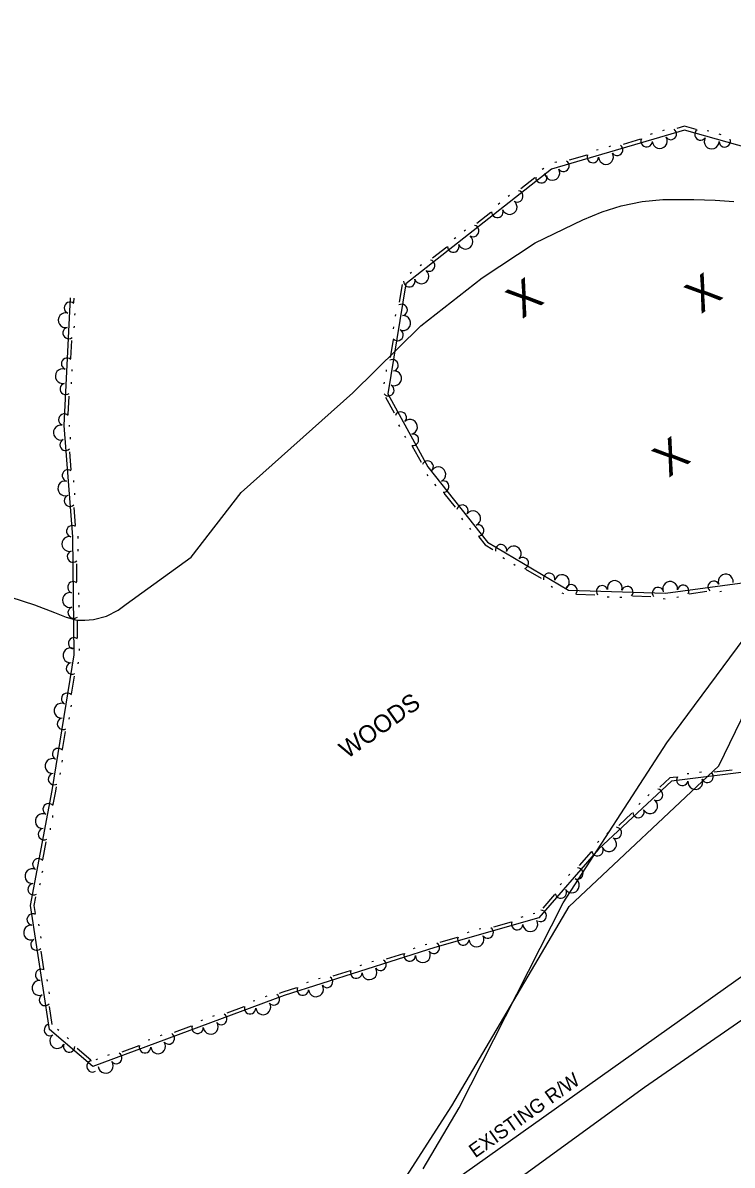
# Model space of a CAD drawing. Extents: x 1577032 to 1581865, y 611492 to 615011.
# Drawn here: x 1578939.3 to 1579100.2, y 612864.7 to 613124 of the extents above; entities that cross this region are included whole.
import ezdxf

# ---------------------------------------------------------------- set-up
doc = ezdxf.new("R2010")
doc.units = 0
for name, color, linetype in [('Exist Hydro Jurisdictional Stream or Body of Water', 7, 'Continuous'), ('Exist Right of Way Line', 7, 'Continuous'), ('Exist Right of Way Line Text', 7, 'Continuous'), ('Exist Utilities Telephone UG FO SUE LOS B', 7, 'Continuous'), ('Exist Utilities Water UG Line SUE LOS B', 7, 'Continuous'), ('Exist Vegetation Tree CELL', 7, 'Continuous'), ('Exist Vegetation Woods Line Text', 7, 'Continuous'), ('Old_Level_11', 7, 'Continuous'), ('Old_Level_8', 7, 'Continuous'), ('Scratch_Level_4', 7, 'Continuous')]:
    doc.layers.add(name, color=color, linetype=linetype)

msp = doc.modelspace()

# ---------------------------------------------------------------- linework, layer by layer
at = {"layer": 'Exist Hydro Jurisdictional Stream or Body of Water'}
msp.add_lwpolyline([(1578931.12, 612995.38), (1578941.94, 612991.91), (1578946.47, 612990.14), (1578949.11, 612989.07), (1578951.53, 612988.4), (1578953.33, 612988.4), (1578955.36, 612988.57), (1578958.28, 612989.3), (1578960.93, 612990.65), (1578962.72, 612992.06), (1578977.46, 613002.69), (1578988.86, 613017.41), (1579014.13, 613040.04), (1579029.62, 613055.18), (1579043.54, 613066.13), (1579055.52, 613074.04), (1579066.31, 613079.26), (1579070.77, 613081.07), (1579075.01, 613082.43), (1579079.81, 613083.39), (1579084.5, 613083.9), (1579091.56, 613083.9), (1579096.37, 613083.73), (1579100.6, 613083.39)], dxfattribs=at)
at = {"layer": 'Exist Right of Way Line'}
msp.add_lwpolyline([(1578124.38, 612213.06), (1579205.66, 612980.92)], dxfattribs=at)
at = {"layer": 'Exist Utilities Telephone UG FO SUE LOS B'}
msp.add_lwpolyline([(1579030.15, 612863.93), (1579038.32, 612877.78), (1579061.9, 612924.28), (1579085.37, 612960.54), (1579115.71, 613001.47), (1579171.23, 613028.63), (1579251.42, 613079.81), (1579314.27, 613123.97)], dxfattribs=at)
at = {"layer": 'Exist Utilities Water UG Line SUE LOS B'}
for p, q in [((1579097.19, 612955.35), (1579118.18, 612998.65)), ((1579063.25, 612923.46), (1579097.19, 612955.35)), ((1579036.61, 612878.17), (1579063.25, 612923.46)), ((1579016.46, 612846.84), (1579036.61, 612878.17))]:
    msp.add_line(p, q, dxfattribs=at)
at = {"layer": 'Old_Level_11'}
for points in [[(1579092.06, 613099.75), (1579089.38, 613100.51), (1579087.67, 613100)], [(1579122.8, 613090.25), (1579089.39, 613099.65), (1579059.25, 613090.73), (1579026.21, 613064.72), (1579022.09, 613039.75), (1579031.17, 613023.18), (1579044.7, 613006.12), (1579063.07, 612995.2), (1579085.08, 612994.52), (1579110.94, 612997.99)], [(1579079.41, 613097.55), (1579075.47, 613096.39)], [(1579082.04, 613098.76), (1579081.65, 613098.65)], [(1579084.8, 613099.58), (1579084.4, 613099.46)], [(1579094.94, 613099.37), (1579094.54, 613099.48)], [(1579097.7, 613098.59), (1579097.31, 613098.7)], [(1579069.85, 613095.16), (1579069.46, 613095.04)], [(1579072.6, 613095.97), (1579072.21, 613095.85)], [(1579060.41, 613092.36), (1579060.02, 613092.25)], [(1579067.22, 613093.95), (1579063.28, 613092.78)], [(1579057.47, 613090.9), (1579057.15, 613090.65)], [(1579055.47, 613088.8), (1579052.25, 613086.27)], [(1579049.74, 613084.81), (1579049.42, 613084.56)], [(1579047.48, 613083.04), (1579047.16, 613082.78)], [(1579045.48, 613080.94), (1579042.26, 613078.4)], [(1579039.75, 613076.95), (1579039.43, 613076.7)], [(1579037.5, 613075.17), (1579037.17, 613074.92)], [(1579035.49, 613073.07), (1579032.27, 613070.54)], [(1579029.76, 613069.08), (1579029.44, 613068.83)], [(1579027.51, 613067.31), (1579027.19, 613067.05)], [(1579025.36, 613064.6), (1579024.69, 613060.56)], [(1579104.69, 612954.14), (1579086.47, 612951.84), (1579069.9, 612936.48), (1579056.38, 612920.84), (1579032.79, 612914.13), (1578998.56, 612903.2), (1578955.18, 612887.09), (1578945.32, 612895.5), (1578941.05, 612923.66), (1578945.95, 612949.77), (1578950.95, 612980.58), (1578950.61, 613007.31), (1578948.63, 613032.57), (1578950.08, 613061.56)], [(1578950.85, 613060.51), (1578950.9, 613061.52)], [(1578951.12, 613057.62), (1578951.14, 613058.03)], [(1579023.82, 613057.79), (1579023.76, 613057.39)], [(1578950.97, 613054.75), (1578950.99, 613055.16)], [(1579023.36, 613054.96), (1579023.29, 613054.56)], [(1578950.21, 613047.81), (1578950.42, 613051.9)], [(1579023.29, 613052.06), (1579022.62, 613048.02)], [(1578950.48, 613044.92), (1578950.5, 613045.33)], [(1579021.75, 613045.25), (1579021.69, 613044.84)], [(1578950.33, 613042.05), (1578950.35, 613042.46)], [(1579021.28, 613042.42), (1579021.22, 613042.01)], [(1578949.57, 613035.11), (1578949.78, 613039.21)], [(1579021.55, 613039.03), (1579023.52, 613035.43)], [(1579024.54, 613032.72), (1579024.74, 613032.36)], [(1578949.87, 613032.38), (1578949.86, 613032.59), (1578949.86, 613032.63)], [(1579025.92, 613030.2), (1579026.12, 613029.84)], [(1578950.1, 613029.52), (1578950.07, 613029.93)], [(1579027.66, 613027.88), (1579029.63, 613024.28)], [(1578950.24, 613022.54), (1578949.92, 613026.63)], [(1578950.87, 613019.71), (1578950.84, 613020.12)], [(1579030.93, 613021.5), (1579031.18, 613021.18)], [(1578951.1, 613016.85), (1578951.06, 613017.25)], [(1579032.71, 613019.25), (1579032.97, 613018.93)], [(1579034.82, 613017.26), (1579037.37, 613014.05)], [(1578951.23, 613009.86), (1578950.91, 613013.95)], [(1579038.83, 613011.54), (1579039.08, 613011.22)], [(1578951.85, 613006.95), (1578951.84, 613007.36), (1578951.84, 613007.45)], [(1579040.61, 613009.3), (1579040.86, 613008.97)], [(1579042.72, 613007.3), (1579044.15, 613005.49), (1579045.95, 613004.42)], [(1578951.88, 613004.08), (1578951.88, 613004.49)], [(1579048.21, 613002.6), (1579048.56, 613002.39)], [(1578951.56, 612997.1), (1578951.51, 613001.21)], [(1579050.68, 613001.14), (1579051.03, 613000.93)], [(1579053.35, 613000.02), (1579056.88, 612997.93)], [(1578952.01, 612994.24), (1578952, 612994.65)], [(1579059.14, 612996.11), (1579059.49, 612995.9)], [(1579061.61, 612994.64), (1579061.96, 612994.43)], [(1579064.94, 612994.32), (1579069.04, 612994.19)], [(1579077.65, 612993.93), (1579081.75, 612993.8)], [(1579090.45, 612994.41), (1579094.51, 612994.96)], [(1579097.41, 612994.93), (1579097.82, 612994.99)], [(1578952.04, 612991.37), (1578952.04, 612991.78)], [(1579071.9, 612993.7), (1579072.31, 612993.68)], [(1579074.77, 612993.61), (1579075.18, 612993.6)], [(1579084.6, 612993.31), (1579085.01, 612993.29)], [(1579087.65, 612993.62), (1579088.06, 612993.68)], [(1578951.72, 612984.39), (1578951.67, 612988.49)], [(1578952.17, 612981.53), (1578952.16, 612981.94)], [(1578951.85, 612978.47), (1578951.92, 612978.87)], [(1578950.33, 612971.65), (1578950.99, 612975.7)], [(1578950.28, 612968.75), (1578950.34, 612969.16)], [(1578949.82, 612965.92), (1578949.89, 612966.32)], [(1578948.3, 612959.1), (1578948.95, 612963.15)], [(1578948.24, 612956.2), (1578948.31, 612956.61)], [(1578947.78, 612953.37), (1578947.85, 612953.78)], [(1579087.6, 612952.81), (1579086.11, 612952.62), (1579083.82, 612950.49)], [(1579090.39, 612953.57), (1579089.99, 612953.52)], [(1579093.24, 612953.93), (1579092.84, 612953.88)], [(1579100.21, 612954.4), (1579096.14, 612953.89)], [(1578946.18, 612946.55), (1578946.76, 612949.63), (1578946.92, 612950.6)], [(1579081.43, 612948.84), (1579081.13, 612948.56)], [(1579077.5, 612944.64), (1579074.49, 612941.85)], [(1579079.33, 612946.89), (1579079.02, 612946.61)], [(1578946.06, 612943.65), (1578946.13, 612944.05)], [(1578945.53, 612940.83), (1578945.6, 612941.23)], [(1579072.11, 612940.2), (1579071.8, 612939.92)], [(1578943.84, 612934.05), (1578944.59, 612938.08)], [(1579070, 612938.25), (1579069.7, 612937.97)], [(1579068.24, 612935.81), (1579065.55, 612932.71)], [(1578943.71, 612931.16), (1578943.79, 612931.56)], [(1579063.37, 612930.8), (1579063.1, 612930.49)], [(1578943.18, 612928.34), (1578943.26, 612928.74)], [(1579061.49, 612928.63), (1579061.22, 612928.32)], [(1578942.16, 612921.82), (1578941.88, 612923.65), (1578942.25, 612925.59)], [(1579059.92, 612926.19), (1579057.24, 612923.09)], [(1579055.46, 612921.86), (1579055.07, 612921.74)], [(1578942.99, 612919.04), (1578942.93, 612919.45)], [(1579050.05, 612919.89), (1579046.11, 612918.77)], [(1579052.7, 612921.07), (1579052.3, 612920.96)], [(1578943.42, 612916.21), (1578943.36, 612916.61)], [(1579037.82, 612916.41), (1579033.88, 612915.29)], [(1579040.47, 612917.59), (1579040.08, 612917.48)], [(1579043.23, 612918.38), (1579042.84, 612918.27)], [(1579028.25, 612913.97), (1579027.86, 612913.84)], [(1579030.98, 612914.84), (1579030.59, 612914.72)], [(1578944.06, 612909.25), (1578943.45, 612913.31)], [(1579018.87, 612910.98), (1579018.48, 612910.85)], [(1579025.64, 612912.71), (1579021.73, 612911.46)], [(1579013.53, 612908.84), (1579009.62, 612907.59)], [(1579016.13, 612910.1), (1579015.74, 612909.98)], [(1578944.9, 612906.47), (1578944.84, 612906.88)], [(1579004.02, 612906.24), (1579003.63, 612906.11)], [(1579006.76, 612907.11), (1579006.37, 612906.99)], [(1578945.33, 612903.64), (1578945.27, 612904.04)], [(1579001.41, 612904.97), (1578998.29, 612903.98), (1578997.48, 612903.68)], [(1578945.97, 612896.68), (1578945.35, 612900.74)], [(1578989.41, 612900.68), (1578985.57, 612899.25)], [(1578991.96, 612902.06), (1578991.57, 612901.92)], [(1578994.65, 612903.06), (1578994.26, 612902.92)], [(1578982.73, 612898.63), (1578982.35, 612898.49)], [(1578947.48, 612895.27), (1578947.17, 612895.54)], [(1578977.49, 612896.25), (1578973.65, 612894.82)], [(1578980.04, 612897.63), (1578979.66, 612897.49)], [(1578949.67, 612893.41), (1578949.36, 612893.67)], [(1578968.12, 612893.21), (1578967.74, 612893.07)], [(1578970.81, 612894.21), (1578970.43, 612894.06)], [(1578954.71, 612888.57), (1578951.59, 612891.23)], [(1578965.58, 612891.82), (1578961.73, 612890.4)], [(1578956.21, 612888.78), (1578955.82, 612888.64)], [(1578958.9, 612889.78), (1578958.51, 612889.64)]]:
    msp.add_lwpolyline(points, dxfattribs=at)
for centre, radius, start, end in [((1579080.82, 613097.12), 1.3, 157.2491, 358.0456), ((1579083.8, 613097.14), 1.69, 182.4443, 30.5168), ((1579086.32, 613098.75), 1.3, 214.9155, 55.7121), ((1579093.02, 613098.63), 1.3, 125.0557, 325.8523), ((1579095.57, 613097.06), 1.69, 150.251, 358.3235), ((1579098.55, 613097.08), 1.3, 182.7222, 23.5188), ((1579074.13, 613095.14), 1.3, 214.9155, 55.7121), ((1579061.94, 613091.53), 1.3, 214.9155, 55.7121), ((1579068.63, 613093.51), 1.3, 157.2491, 358.0456), ((1579071.61, 613093.54), 1.69, 182.4443, 30.5168), ((1579059.42, 613089.93), 1.69, 182.4443, 30.5168), ((1579056.95, 613088.92), 1.3, 178.987, 19.7836), ((1579051.47, 613084.61), 1.3, 236.6535, 77.4501), ((1579049.72, 613082.19), 1.69, 204.1823, 52.2548), ((1579046.96, 613081.06), 1.3, 178.987, 19.7836), ((1579041.48, 613076.74), 1.3, 236.6535, 77.4501), ((1579039.73, 613074.32), 1.69, 204.1823, 52.2548), ((1579036.97, 613073.19), 1.3, 178.987, 19.7836), ((1579031.49, 613068.88), 1.3, 236.6535, 77.4501), ((1579029.74, 613066.46), 1.69, 204.1823, 52.2548), ((1579026.98, 613065.33), 1.3, 178.987, 19.7836), ((1578949.97, 613059.32), 1.3, 47.892, 248.6886), ((1579025.24, 613058.81), 1.3, 279.0627, 119.8593), ((1578949.01, 613056.49), 1.69, 73.0873, 281.1598), ((1579025.58, 613055.84), 1.69, 246.5915, 94.664), ((1578949.68, 613053.58), 1.3, 105.5585, 306.355), ((1579024.3, 613053.14), 1.3, 221.3962, 62.1928), ((1578949.33, 613046.62), 1.3, 47.892, 248.6886), ((1579023.17, 613046.26), 1.3, 279.0627, 119.8593), ((1578948.37, 613043.79), 1.69, 73.0873, 281.1598), ((1579023.51, 613043.3), 1.69, 246.5915, 94.664), ((1578949.04, 613040.89), 1.3, 105.5585, 306.355), ((1579022.23, 613040.6), 1.3, 221.3962, 62.1928), ((1579025.03, 613034.39), 1.3, 317.1373, 157.9339), ((1578947.93, 613030.99), 1.69, 80.4616, 288.5341), ((1578948.69, 613033.92), 1.3, 47.892, 248.6886), ((1579027.13, 613032.27), 1.69, 284.6661, 132.7386), ((1579027.79, 613029.35), 1.3, 259.4709, 100.2674), ((1578948.97, 613028.2), 1.3, 112.9328, 313.7294), ((1578949.52, 613021.25), 1.3, 55.2663, 256.0629), ((1579031.14, 613023.24), 1.3, 317.1373, 157.9339), ((1579033.55, 613021.49), 1.69, 294.3826, 142.4551), ((1578948.92, 613018.32), 1.69, 80.4616, 288.5341), ((1579034.69, 613018.73), 1.3, 269.1874, 109.9839), ((1578949.97, 613015.52), 1.3, 112.9328, 313.7294), ((1579039.03, 613013.27), 1.3, 326.8538, 167.6504), ((1579041.45, 613011.53), 1.69, 294.3826, 142.4551), ((1578950.51, 613008.57), 1.3, 55.2663, 256.0629), ((1579042.59, 613008.77), 1.3, 269.1874, 109.9839), ((1578949.81, 613005.7), 1.69, 76.6864, 284.7589), ((1579047.78, 613004.29), 1.3, 347.7118, 188.5083), ((1579050.67, 613003.53), 1.69, 315.2406, 163.3131), ((1578950.67, 613002.84), 1.3, 109.1576, 309.9541), ((1579052.72, 613001.35), 1.3, 290.0453, 130.8419), ((1579058.71, 612997.79), 1.3, 347.7118, 188.5083), ((1578950.76, 612995.86), 1.3, 51.4911, 252.2877), ((1579061.6, 612997.03), 1.69, 315.2406, 163.3131), ((1579063.74, 612995.18), 1.3, 319.0055, 159.8021), ((1579073.6, 612995.7), 1.69, 344.2008, 192.2733), ((1579086.16, 612995.49), 1.69, 353.6075, 201.6799), ((1579096.03, 612995.99), 1.3, 26.0786, 226.8752), ((1579098.76, 612997.18), 1.69, 353.6075, 201.6799), ((1578949.97, 612992.98), 1.69, 76.6864, 284.7589), ((1579070.71, 612994.96), 1.3, 16.672, 217.4685), ((1579076.44, 612994.79), 1.3, 319.0055, 159.8021), ((1579083.41, 612994.57), 1.3, 16.672, 217.4685), ((1579089.12, 612995.06), 1.3, 328.4122, 169.2087), ((1578950.83, 612990.12), 1.3, 109.1576, 309.9541), ((1578950.92, 612983.15), 1.3, 51.4911, 252.2877), ((1578950.09, 612980.42), 1.69, 66.7534, 274.8259), ((1578950.44, 612977.45), 1.3, 99.2246, 300.0212), ((1578949.33, 612970.57), 1.3, 41.5581, 242.3547), ((1578948.06, 612967.87), 1.69, 66.7534, 274.8259), ((1578948.41, 612964.9), 1.3, 99.2246, 300.0212), ((1578947.29, 612958.02), 1.3, 41.5581, 242.3547), ((1578946.02, 612955.32), 1.69, 66.7534, 274.8259), ((1578946.37, 612952.35), 1.3, 99.2246, 300.0212), ((1579088.92, 612952.15), 1.3, 147.9897, 348.7863), ((1579094.62, 612952.87), 1.3, 205.6562, 46.4527), ((1579083.17, 612948.77), 1.3, 241.2513, 82.0479), ((1579091.87, 612951.69), 1.69, 173.185, 21.2575), ((1579081.62, 612946.22), 1.69, 208.7802, 56.8526), ((1578945.15, 612945.49), 1.3, 40.131, 240.9276), ((1579078.96, 612944.87), 1.3, 183.5849, 24.3814), ((1578943.81, 612942.82), 1.69, 65.3263, 273.3988), ((1578944.09, 612939.85), 1.3, 97.7975, 298.594), ((1579073.84, 612940.13), 1.3, 241.2513, 82.0479), ((1579069.66, 612936.2), 1.3, 189.9259, 30.7224), ((1579072.3, 612937.58), 1.69, 208.7802, 56.8526), ((1578942.8, 612933), 1.3, 40.131, 240.9276), ((1578941.47, 612930.33), 1.69, 65.3263, 273.3988), ((1579065.1, 612930.93), 1.3, 247.5923, 88.3889), ((1579063.85, 612928.22), 1.69, 215.1212, 63.1936), ((1578941.74, 612927.35), 1.3, 97.7975, 298.594), ((1579061.35, 612926.59), 1.3, 189.9259, 30.7224), ((1578941.53, 612920.48), 1.3, 59.3802, 260.1767), ((1579056.79, 612921.31), 1.3, 247.5923, 88.3889), ((1578941.15, 612917.52), 1.69, 84.5755, 292.6479), ((1579051.46, 612919.44), 1.3, 156.6481, 357.4446), ((1579054.44, 612919.44), 1.69, 181.8433, 29.9158), ((1579039.23, 612915.96), 1.3, 156.6481, 357.4446), ((1579042.22, 612915.96), 1.69, 181.8433, 29.9158), ((1579044.75, 612917.53), 1.3, 214.3145, 55.1111), ((1578942.39, 612914.8), 1.3, 117.0466, 317.8432), ((1579032.53, 612914.04), 1.3, 216.1362, 56.9328), ((1579020.42, 612910.18), 1.3, 216.1362, 56.9328), ((1579027.06, 612912.3), 1.3, 158.4698, 359.2663), ((1579030.04, 612912.39), 1.69, 183.665, 31.7375), ((1578943.44, 612907.91), 1.3, 59.3802, 260.1767), ((1579014.95, 612908.43), 1.3, 158.4698, 359.2663), ((1579017.93, 612908.52), 1.69, 183.665, 31.7375), ((1578943.05, 612904.95), 1.69, 84.5755, 292.6479), ((1579008.3, 612906.31), 1.3, 216.1362, 56.9328), ((1578944.3, 612902.23), 1.3, 117.0466, 317.8432), ((1578996.23, 612902.34), 1.3, 218.8152, 59.6118), ((1579002.83, 612904.57), 1.3, 158.4698, 359.2663), ((1579005.82, 612904.66), 1.69, 183.665, 31.7375), ((1578990.85, 612900.34), 1.3, 161.1487, 1.9453), ((1578993.83, 612900.57), 1.69, 186.344, 34.4165), ((1578984.31, 612897.91), 1.3, 218.8152, 59.6118), ((1578945.44, 612895.4), 1.3, 100.3272, 301.1237), ((1578978.93, 612895.91), 1.3, 161.1487, 1.9453), ((1578981.91, 612896.14), 1.69, 186.344, 34.4165), ((1578947.09, 612892.91), 1.69, 125.5225, 333.5949), ((1578972.4, 612893.48), 1.3, 218.8152, 59.6118), ((1578949.81, 612891.67), 1.3, 157.9936, 358.7902), ((1578960.48, 612889.06), 1.3, 218.8152, 59.6118), ((1578967.01, 612891.48), 1.3, 161.1487, 1.9453), ((1578969.99, 612891.71), 1.69, 186.344, 34.4165), ((1578955.11, 612887.15), 1.3, 100.3272, 301.1237), ((1578958.07, 612887.29), 1.69, 186.344, 34.4165)]:
    msp.add_arc(centre, radius, start, end, dxfattribs=at)
at = {"layer": 'Old_Level_8'}
msp.add_lwpolyline([(1578949, 612778.47), (1578966.35, 612793.38), (1578989.45, 612813.51), (1579016.65, 612835.66), (1579050.7, 612860.86), (1579080.37, 612882.46), (1579102.44, 612897.69), (1579125.77, 612910.99), (1579158.9, 612927.19), (1579180.94, 612938.03), (1579196.01, 612946.6), (1579242.04, 612993.41)], dxfattribs=at)
at = {"layer": 'Scratch_Level_4'}
for points in [[(1578991.07, 612725.28), (1579012.35, 612739.17), (1579031.33, 612751.38), (1579051.46, 612763.88), (1579075.01, 612777.37), (1579095.02, 612788.96), (1579114.97, 612802.08), (1579136.91, 612817.74), (1579159.19, 612837), (1579170.02, 612846.94), (1579184.02, 612858.83), (1579200.33, 612873.19), (1579214.2, 612885.73), (1579229.83, 612902.71)], [(1579027.98, 612739.86), (1579035.54, 612744.72), (1579055.5, 612757.12), (1579078.94, 612770.55), (1579099.16, 612782.26), (1579119.42, 612795.58), (1579141.78, 612811.55), (1579164.43, 612831.12), (1579175.24, 612841.04), (1579189.17, 612852.88), (1579205.57, 612867.32), (1579219.75, 612880.13), (1579235.83, 612897.6)]]:
    msp.add_spline(points, degree=3, dxfattribs=at)

# ---------------------------------------------------------------- texts
at = {"layer": 'Exist Right of Way Line Text'}
msp.add_text('EXISTING R/W', height=3.2, rotation=35.38, dxfattribs=at).set_placement((1579041.94, 612866.27))
at = {"layer": 'Exist Vegetation Tree CELL'}
for p in [(1579093.12, 613057.79), (1579052.56, 613056.68), (1579085.8, 613020.64)]:
    msp.add_text('X', height=7.38, rotation=36.1764, dxfattribs=at).set_placement(p)
at = {"layer": 'Exist Vegetation Woods Line Text'}
msp.add_text('WOODS', height=4, rotation=35.38, dxfattribs=at).set_placement((1579012.88, 612956.84))

doc.saveas('drawing.dxf')
